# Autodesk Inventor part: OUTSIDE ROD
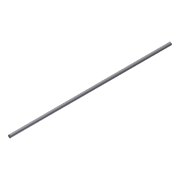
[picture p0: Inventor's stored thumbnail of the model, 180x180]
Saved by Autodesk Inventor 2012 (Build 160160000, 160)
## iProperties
Created: 2011-05
Part Number: OUTSIDE ROD
Material: Stainless Steel, 440C
Document SubType Name: Modeling
Designer: Dimitris
Mass: 1952.41 g
Surface Area: 564.921 cm^2
Volume: 251.924 cm^3
Density: 7.75 g/cm^3
Author: Dimitris
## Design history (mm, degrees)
sketch "Sketch1"
  geometry: C1 r 9 at (0, 0); 1 further point
  constraints: 1 centre point, 1 coincident
  dimensions: "d0" = 18 diameter of C1
extrude "Extrusion1" new body sketch "Sketch1" taper "d2" = 0 deg; stored distance "Length" = 1000
sketch "Sketch5"
  geometry: 1 further point
hole "Hole6" sketch "Sketch5" at (0, 0) diameter "d24" = 8.376; stored, may be unused: countersink angle "d28" = 90 deg, drill point angle "d30" = 118 deg; dims "d25" = 6, "d26" = 4, "d27" = 2, "d29" = 20
hole "Hole7" diameter "d33" = 8.376; stored, may be unused: countersink angle "d37" = 90 deg, drill point angle "d39" = 118 deg; dims "d31" = 10, "d32" = 10, "d34" = 15, "d35" = 4, "d36" = 2, "d38" = 20
body "Solid1"
